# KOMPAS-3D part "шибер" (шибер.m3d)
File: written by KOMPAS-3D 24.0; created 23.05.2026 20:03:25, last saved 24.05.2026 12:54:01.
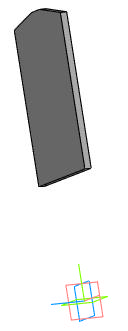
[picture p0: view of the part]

Document properties: Автор: R2D2; Полное имя файла: E:\Работа\Зайцев\GVKR1331E-1W-Fb-2P Задвижка шиберная DN.ru Ду50-300 Ру16-10-6\исходные материалы\DN200\шибер.m3d

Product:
- Part/product: шибер
    Масса: 2.843453
    Раздел спецификации: Прочие изделия
    Примечание: D040-08800

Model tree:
1. Эскиз:5  (with: Грань.Элемент выдавливания:1, Вершина.Элемент выдавливания:15)
2. Элемент выдавливания:6
     Расстояние 1 = 10

Referenced files in E:\Работа\Зайцев\GVKR1331E-1W-Fb-2P Задвижка шиберная DN.ru Ду50-300 Ру16-10-6\исходные материалы\DN200\: GVKR1331E-1W-Fb-2P Задвижка шиберная с выдвижным штоком DN.ru Ду200 Ру10.a3d
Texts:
  Затвор дисковый DN.ru Ду Ру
